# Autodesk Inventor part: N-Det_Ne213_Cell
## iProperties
Shininess: 64.0
Length Units: 11269
Angle Units: 11279
Time Units: 11290
Mass Units: 11283
Length Display Precision: 3
Angle Display Precision: 2
Compacted: True
Part Number: N-Det_Ne213_Cell
Document SubType Name: Modeling
Created: 2005-04
Designer: John Blackburn
Manufacturer: Standard
Standards Organization: Custom
Material: NE-213
Density: 0.0
Volumn: 0.0
Area: 0.0
PropertySet Name: Model Information
Control State: 0
Master: False
Checked Out: False
Author: John Blackburn
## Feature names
1. Extrusion1
